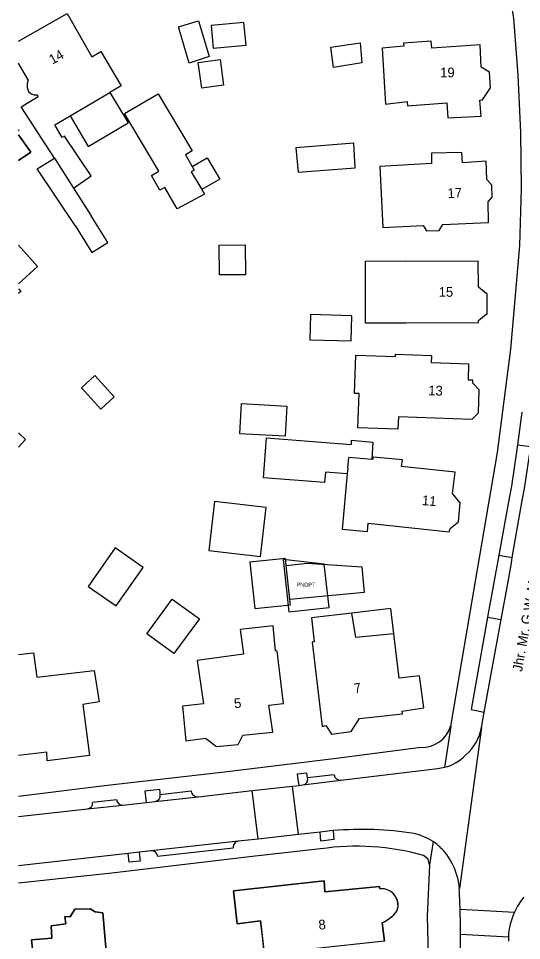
# Model space of a CAD drawing. Extents: x 194485 to 197793, y 468269 to 470822.
# Drawn here: x 194485.4 to 194547.5, y 470088.6 to 470202.3 of the extents above; entities that cross this region are included whole.
import ezdxf

# ---------------------------------------------------------------- set-up
doc = ezdxf.new("R2010")
doc.units = 0
for name, color, linetype in [('BAG plantopografie panden grensvlak pand', 7, 'Continuous'), ('BAG plantopografie panden kenmerkpunt', 7, 'Continuous'), ('BGT grensvlak gebouwinstallatie plus 1', 7, 'Continuous'), ('BGT grensvlak overig bouwwerk uitbreiding populatie', 7, 'Continuous'), ('BGT grensvlak pand op maaiveld', 7, 'Continuous'), ('BGT grensvlak pand op maaiveld LR', 7, 'Continuous'), ('BGT grensvlak wegdeel', 7, 'Continuous'), ('BGT tekst huisnummerreeks', 7, 'Continuous'), ('BGT tekst openbare ruimte label weg', 7, 'Continuous'), ('GEM grensvlak beperking object', 7, 'Continuous')]:
    doc.layers.add(name, color=color, linetype=linetype)

msp = doc.modelspace()

# ---------------------------------------------------------------- linework, layer by layer
at = {"layer": 'BAG plantopografie panden grensvlak pand'}
msp.add_lwpolyline([(194518.04, 470135.61), (194518.74, 470129.14), (194523.71, 470129.68), (194523.13, 470135.03), (194518.04, 470135.61)], dxfattribs=at)
at = {"layer": 'BGT grensvlak gebouwinstallatie plus 1'}
for p, q in [((194496.69, 470193.16), (194498.93, 470189.43)), ((194506.84, 470184.06), (194508.7, 470185.11)), ((194508.7, 470185.11), (194510.26, 470182.48)), ((194510.26, 470182.48), (194508.03, 470181.19)), ((194487.77, 470171.73), (194485.41, 470174.33)), ((194485.41, 470169.59), (194487.77, 470171.73)), ((194526.46, 470150.3), (194526.42, 470149.77)), ((194526.46, 470150.3), (194529.12, 470150.08)), ((194529.12, 470150.08), (194528.97, 470147.94)), ((194525.96, 470146.17), (194523.27, 470146.38)), ((194501.25, 470126.44), (194504.37, 470130.72)), ((194504.37, 470130.72), (194507.72, 470128.28)), ((194507.72, 470128.28), (194504.59, 470124)), ((194504.59, 470124), (194501.25, 470126.44))]:
    msp.add_line(p, q, dxfattribs=at)
for points in [[(194491.77, 470190.27), (194494.03, 470186.5), (194498.93, 470189.43)], [(194523.27, 470146.38), (194523.17, 470145.09), (194515.62, 470145.68), (194516, 470150.59), (194526.42, 470149.77)], [(194497.35, 470137.03), (194494.03, 470132.29), (194497.48, 470129.88), (194500.79, 470134.61), (194497.35, 470137.03)], [(194531.72, 470126.43), (194531.35, 470129.55), (194526.54, 470128.98)]]:
    msp.add_lwpolyline(points, dxfattribs=at)
at = {"layer": 'BGT grensvlak overig bouwwerk uitbreiding populatie'}
for p, q in [((194507.59, 470196.86), (194510.27, 470197.23)), ((194508.04, 470193.7), (194507.59, 470196.86)), ((194510.27, 470197.23), (194510.71, 470194.08)), ((194510.71, 470194.08), (194508.04, 470193.7)), ((194510.18, 470174.35), (194513.36, 470174.37)), ((194510.2, 470170.68), (194510.18, 470174.35)), ((194513.36, 470174.37), (194513.39, 470170.7)), ((194513.39, 470170.7), (194510.2, 470170.68)), ((194493.17, 470156.77), (194494.82, 470158.28)), ((194494.82, 470158.28), (194497.21, 470155.64)), ((194495.56, 470154.14), (194493.17, 470156.77)), ((194497.21, 470155.64), (194495.56, 470154.14)), ((194485.41, 470151.2), (194486.28, 470150.38)), ((194486.28, 470150.38), (194485.41, 470149.46))]:
    msp.add_line(p, q, dxfattribs=at)
at = {"layer": 'BGT grensvlak pand op maaiveld'}
for p, q in [((194486.63, 470194.74), (194485.41, 470196.8)), ((194491.77, 470190.27), (194496.69, 470193.16)), ((194506.72, 470183.38), (194508.03, 470181.19)), ((194492.22, 470181.37), (194494.39, 470177.97)), ((194526.03, 470146.85), (194526.15, 470148.17)), ((194528.97, 470147.94), (194526.15, 470148.17)), ((194526.03, 470146.85), (194525.96, 470146.17))]:
    msp.add_line(p, q, dxfattribs=at)
for points in [[(194485.41, 470199.49), (194491.4, 470202.92), (194494.46, 470197.58), (194495.57, 470198.23), (194498.08, 470193.97), (194496.69, 470193.16)], [(194505.15, 470201.27), (194507.62, 470201.98), (194508.94, 470197.61), (194506.45, 470196.8), (194505.15, 470201.27)], [(194509.43, 470198.63), (194513.48, 470198.99), (194513.22, 470201.8), (194509.17, 470201.44), (194509.43, 470198.63)], [(194524.28, 470196.25), (194523.92, 470198.75), (194527.54, 470199.27), (194527.74, 470196.81), (194524.28, 470196.25)], [(194542.49, 470190.26), (194542.3, 470192.22), (194542.64, 470192.24), (194543.64, 470193.72), (194543.5, 470195.68), (194542.48, 470196.3), (194542.33, 470199.02), (194536.37, 470198.62), (194536.29, 470199.48), (194532.91, 470199.24), (194532.93, 470198.89), (194530.27, 470198.63), (194530.67, 470191.74), (194533.36, 470192.07), (194533.38, 470191.51), (194538.24, 470191.89), (194538.38, 470190.03), (194542.49, 470190.26)], [(194486.63, 470194.74), (194486.48, 470194.28), (194486.48, 470193.79), (194486.65, 470193.28), (194486.99, 470193), (194487.37, 470192.87), (194487.73, 470192.87)], [(194489.84, 470185.07), (194485.76, 470191.4), (194487.85, 470192.67), (194487.73, 470192.87)], [(194503.47, 470181.47), (194502.86, 470181.11), (194501.81, 470182.95), (194502.74, 470183.48), (194498.49, 470190.58), (194502.63, 470193.02), (194506.83, 470185.97), (194506.01, 470185.49), (194506.84, 470184.06)], [(194492.22, 470181.37), (194494.38, 470182.88), (194491.09, 470187.8), (194490.79, 470187.6), (194489.89, 470189.17), (194491.77, 470190.27)], [(194485.41, 470188.43), (194485.48, 470188.47), (194485.41, 470188.56)], [(194485.41, 470184.78), (194486.92, 470185.83), (194485.41, 470187.93)], [(194526.95, 470183.88), (194526.77, 470186.93), (194519.62, 470186.36), (194519.92, 470183.36), (194526.95, 470183.88)], [(194492.41, 470176.76), (194487.73, 470183.74), (194489.84, 470185.07)], [(194543.36, 470177.15), (194543.32, 470179.7), (194543.82, 470180.27), (194543.8, 470181.76), (194543.15, 470182.42), (194543.07, 470184.7), (194540.17, 470184.51), (194540.1, 470185.75), (194536.33, 470185.68), (194536.34, 470184.41), (194529.96, 470184.04), (194530.33, 470176.51), (194535.31, 470176.76), (194535.73, 470176.11), (194537.31, 470176.17), (194537.73, 470176.91), (194543.36, 470177.15)], [(194506.84, 470184.06), (194507.1, 470183.61), (194506.72, 470183.38)], [(194508.03, 470181.19), (194508.37, 470180.63), (194504.99, 470178.83), (194503.47, 470181.47)], [(194492.41, 470176.76), (194494.45, 470173.45), (194496.43, 470174.67), (194494.39, 470177.97)], [(194533.22, 470164.79), (194533.22, 470164.74), (194528.22, 470164.73), (194528.19, 470172.38), (194533.08, 470172.4), (194533.08, 470172.35)], [(194533.22, 470164.79), (194542.15, 470164.83), (194542.15, 470165.05), (194543.1, 470165.83), (194543.2, 470165.83), (194543.19, 470168.39), (194543.09, 470168.39), (194542.14, 470169.17), (194542.12, 470172.38), (194533.08, 470172.35)], [(194485.41, 470168.95), (194485.7, 470168.64), (194485.41, 470168.38)], [(194526.43, 470162.54), (194526.52, 470165.64), (194521.42, 470165.78), (194521.33, 470162.68), (194526.43, 470162.54)], [(194541.3, 470152.87), (194532.27, 470153.18), (194532.21, 470151.67), (194527.27, 470151.84), (194527.41, 470156.05), (194526.86, 470156.07), (194527.02, 470160.78), (194531.86, 470160.62)], [(194541.3, 470152.87), (194542.15, 470153.66), (194542.24, 470156.5), (194541.45, 470157.35), (194541.46, 470157.69), (194540.89, 470157.71), (194540.95, 470159.67), (194536.36, 470159.83), (194536.39, 470160.7), (194531.87, 470160.85), (194531.86, 470160.62)], [(194518.32, 470150.8), (194512.71, 470151.1), (194512.91, 470154.82)], [(194512.91, 470154.82), (194518.51, 470154.52), (194518.32, 470150.8)], [(194525.96, 470146.17), (194525.35, 470139.32), (194528.44, 470139.06), (194528.55, 470140.08), (194538.54, 470139.02), (194538.63, 470139.44), (194539.68, 470140.24), (194539.89, 470142.6), (194538.92, 470143.72), (194539.26, 470146.35), (194532.66, 470147.07), (194532.77, 470147.89), (194529.14, 470148.2), (194529.08, 470147.93), (194528.97, 470147.94)], [(194515.27, 470135.99), (194515.96, 470142.02), (194509.59, 470142.75), (194508.9, 470136.72), (194515.27, 470135.99)], [(194518.43, 470134.84), (194518.34, 470135.72), (194513.96, 470135.26), (194514.57, 470129.55), (194518.94, 470130.01), (194518.88, 470130.66)], [(194518.43, 470134.84), (194521.01, 470135.15), (194527.75, 470134.7), (194528.04, 470131.55), (194518.88, 470130.66)], [(194526.54, 470128.98), (194521.56, 470128.41), (194521.89, 470125.44), (194521.63, 470125.42), (194522.87, 470115.03), (194523.33, 470115.13), (194524.02, 470114.09), (194526.42, 470114.38)], [(194531.72, 470126.43), (194527, 470126), (194526.54, 470128.98)], [(194512.52, 470112.78), (194513.1, 470113.94), (194516.78, 470114.33), (194516.27, 470117.64), (194518.08, 470117.86), (194517.33, 470124.32), (194517.13, 470124.34), (194516.84, 470127.41), (194512.77, 470126.96), (194513.17, 470123.94), (194507.45, 470123.16), (194508.25, 470117.8), (194505.63, 470117.53), (194506.07, 470113.25), (194508.48, 470113.56), (194509.82, 470112.54), (194512.52, 470112.78)], [(194526.42, 470114.38), (194527.47, 470115.99), (194532.77, 470116.58), (194532.74, 470116.89), (194535.39, 470117.31), (194534.87, 470121.27), (194532.36, 470120.99), (194531.72, 470126.43)], [(194485.41, 470123.87), (194487.26, 470124.1), (194487.68, 470121.11), (194494.76, 470121.9), (194495.36, 470118.07), (194493.36, 470117.73), (194494.18, 470111.46)], [(194494.18, 470111.46), (194488.97, 470110.78), (194488.9, 470111.85), (194485.41, 470111.43)], [(194530.28, 470090.83), (194530.54, 470088.54), (194521.38, 470087.58), (194521.74, 470084.25), (194513.83, 470083.49), (194513.4, 470086.9), (194515.72, 470087.08), (194515.49, 470089.18), (194515.28, 470091.04), (194512.37, 470090.67), (194511.93, 470094.75), (194523.11, 470096.01), (194523.2, 470094.65), (194529.94, 470095.3), (194529.97, 470095.01)], [(194496.66, 470082.58), (194495.83, 470092.04), (194494.89, 470092.17), (194494.27, 470092.55), (194492.37, 470092.48), (194491.81, 470091.55), (194491.14, 470091.58), (194491.27, 470090.69), (194489.44, 470090.43), (194489.51, 470088.92), (194487.02, 470088.71), (194487.67, 470082.9)]]:
    msp.add_lwpolyline(points, dxfattribs=at)
for centre, radius, start, end in [((194530.18, 470092.97), 2.04, 66.6153, 95.8839), ((194530.17, 470092.98), 2.05, 22.5532, 66.2765), ((194530.33, 470092.98), 1.9, 336.9753, 24.3772), ((194528.36, 470095.12), 4.7, 294.0189, 322.132)]:
    msp.add_arc(centre, radius, start, end, dxfattribs=at)
at = {"layer": 'BGT grensvlak pand op maaiveld LR'}
for p, q in [((194489.84, 470185.07), (194492.22, 470181.37)), ((194518.88, 470130.66), (194518.43, 470134.84))]:
    msp.add_line(p, q, dxfattribs=at)
at = {"layer": 'BGT grensvlak wegdeel'}
for p, q in [((194547.47, 470153.76), (194546.93, 470149.75)), ((194546.93, 470149.75), (194546.23, 470144.65)), ((194546.93, 470149.75), (194548.58, 470149.53)), ((194546.23, 470144.65), (194545.94, 470143.16)), ((194545.94, 470143.16), (194544.66, 470136.15)), ((194544.66, 470136.15), (194543.26, 470128.5)), ((194544.66, 470136.15), (194546.31, 470135.84)), ((194542.82, 470116.79), (194544.93, 470128.19)), ((194543.26, 470128.5), (194544.93, 470128.19)), ((194542.5, 470114.91), (194542.82, 470116.79)), ((194538.71, 470115.06), (194537.93, 470109.98)), ((194542.5, 470114.91), (194539.78, 470095.06)), ((194535.05, 470112.43), (194524.65, 470111.09)), ((194525.17, 470108.4), (194537.1, 470109.85)), ((194524.34, 470109.05), (194521.07, 470108.68)), ((194514.22, 470107.11), (194519.19, 470107.67)), ((194519.19, 470107.67), (194519.98, 470107.76)), ((194519.93, 470101.7), (194519.19, 470107.67)), ((194519.98, 470107.76), (194520.5, 470107.81)), ((194520.5, 470107.81), (194525.17, 470108.4)), ((194502.27, 470105.78), (194507.56, 470106.36)), ((194506.72, 470107.06), (194502.9, 470106.6)), ((194507.56, 470106.36), (194514.22, 470107.11)), ((194514.96, 470101.14), (194514.22, 470107.11)), ((194493.92, 470104.85), (194498.29, 470105.33)), ((194494.56, 470105.67), (194497.49, 470106.03)), ((194498.29, 470105.33), (194501.17, 470105.66)), ((194501.17, 470105.66), (194502.27, 470105.78)), ((194485.41, 470103.92), (194493.92, 470104.85)), ((194522.6, 470102), (194519.93, 470101.7)), ((194524.23, 470102.18), (194522.6, 470102)), ((194512.52, 470100.87), (194501.78, 470099.69)), ((194514.96, 470101.14), (194512.52, 470100.87)), ((194519.93, 470101.7), (194514.96, 470101.14)), ((194536.54, 470100.84), (194536.1, 470097.98)), ((194501.78, 470099.69), (194500.29, 470099.53)), ((194502.57, 470099.04), (194511.9, 470100.07)), ((194498.96, 470099.38), (194485.41, 470097.86)), ((194500.29, 470099.53), (194498.96, 470099.38)), ((194539.88, 470092.49), (194546.58, 470092.14)), ((194539.92, 470089.4), (194545.83, 470089.08))]:
    msp.add_line(p, q, dxfattribs=at)
for points in [[(194538.71, 470115.06), (194541.76, 470132.92), (194544.49, 470148.78), (194546.12, 470161.52), (194547.24, 470174.3), (194547.43, 470181.27), (194547.35, 470188.24), (194547.04, 470195.29), (194546.51, 470202.32), (194543.84, 470218.01)], [(194546.31, 470135.84), (194547.52, 470142.86), (194547.81, 470144.34), (194548.58, 470149.53)], [(194544.93, 470128.19), (194545.67, 470132.2), (194546.2, 470135.15), (194546.31, 470135.84)], [(194543.26, 470128.5), (194541.25, 470117.13), (194542.82, 470116.79)], [(194524.65, 470111.09), (194510.82, 470109.39), (194496.03, 470107.7), (194485.41, 470106.38)], [(194521.07, 470108.68), (194520.99, 470109.28), (194519.8, 470109.12), (194519.88, 470108.53), (194519.98, 470107.76)], [(194502.9, 470106.6), (194502.87, 470106.9), (194502.83, 470107.23), (194501, 470107.06), (194501.17, 470105.66)], [(194524.23, 470102.18), (194524.3, 470101.07), (194522.7, 470100.9), (194522.6, 470102)], [(194522.67, 470099.94), (194514.61, 470099.05), (194496.91, 470096.93), (194485.41, 470095.69)], [(194500.29, 470099.53), (194500.41, 470098.43), (194499.07, 470098.29), (194498.96, 470099.38)], [(194536.1, 470097.98), (194535.93, 470098.68), (194535.36, 470099.13)], [(194536.1, 470097.98), (194535.82, 470091.6), (194535.96, 470085.36), (194536.77, 470077.26), (194537.92, 470069.2), (194543.74, 470039.31)]]:
    msp.add_lwpolyline(points, dxfattribs=at)
for centre, radius, start, end in [((194535.16, 470116.13), 3.7, 268.1998, 343.2065), ((194536.98, 470115.79), 5.59, 310.0632, 350.935), ((194536.68, 470115.21), 5.37, 283.4937, 316.6179), ((194536.67, 470115.27), 5.43, 274.6011, 283.4717), ((194520.37, 470108.51), 0.714, 280.3741, 14.2875), ((194525.12, 470109.18), 0.787, 189.3304, 274.0759), ((194502.15, 470106.52), 0.755, 279.0586, 6.1667), ((194507.49, 470107.13), 0.774, 184.8553, 274.985), ((194493.82, 470105.59), 0.744, 277.2792, 5.9174), ((194498.24, 470106.09), 0.755, 184.3586, 273.3816), ((194527.77, 470061.02), 41.31, 81.0535, 94.9102), ((194532.55, 470094.7), 7.31, 57.0045, 77.0244), ((194512.61, 470100.16), 0.714, 97.1147, 187.9062), ((194532.02, 470094.3), 7.94, 43.1335, 55.3852), ((194501.85, 470098.97), 0.724, 5.0514, 95.8926), ((194527.08, 470069.33), 30.92, 74.4757, 98.2002), ((194531.65, 470094.39), 8.16, 4.7217, 40.8765), ((194412.83, 470088.98), 127.09, 1.5839, 2.7424), ((194554.15, 470088.66), 8.33, 140.246, 155.3379), ((194420.08, 470089.32), 119.84, 0.0351, 1.5174), ((194554.2, 470088.64), 8.39, 155.362, 176.9981), ((194417.89, 470089.39), 122.03, 358.8636, 0.0004), ((194554.88, 470088.65), 9.06, 177.2331, 180.6412)]:
    msp.add_arc(centre, radius, start, end, dxfattribs=at)
at = {"layer": 'GEM grensvlak beperking object'}
for points in [[(194485.41, 470188.56), (194485.48, 470188.47), (194485.41, 470188.43)], [(194485.41, 470187.93), (194486.92, 470185.83), (194485.41, 470184.78)], [(194485.41, 470123.87), (194487.26, 470124.1), (194487.68, 470121.11), (194494.76, 470121.9), (194495.36, 470118.07), (194493.36, 470117.73), (194494.18, 470111.46), (194488.97, 470110.78), (194488.9, 470111.85), (194485.41, 470111.43)], [(194530.54, 470088.54), (194530.28, 470090.83), (194530.79, 470091.1), (194531.26, 470091.42), (194531.69, 470091.8), (194532.07, 470092.24), (194532.17, 470092.53), (194532.22, 470092.84), (194532.21, 470093.16), (194532.16, 470093.47), (194532.05, 470093.76), (194531.87, 470094.1), (194531.63, 470094.41), (194531.33, 470094.66), (194530.99, 470094.85), (194530.66, 470094.96), (194530.32, 470095.01), (194529.97, 470095.01), (194529.94, 470095.3), (194523.2, 470094.65), (194523.11, 470096.01), (194511.93, 470094.75)], [(194511.93, 470094.75), (194512.37, 470090.67), (194515.28, 470091.04), (194515.72, 470087.08)], [(194487.67, 470082.9), (194487.02, 470088.71), (194489.51, 470088.92), (194489.44, 470090.43), (194491.27, 470090.69), (194491.14, 470091.58), (194491.81, 470091.55), (194492.37, 470092.48), (194494.27, 470092.55), (194494.89, 470092.17), (194495.83, 470092.04), (194496.66, 470082.58)]]:
    msp.add_lwpolyline(points, dxfattribs=at)

# ---------------------------------------------------------------- texts
at = {"layer": 'BAG plantopografie panden kenmerkpunt'}
msp.add_text('PNDPT', height=0.5, dxfattribs=at).set_placement((194519.7, 470132.24))
at = {"layer": 'BGT tekst huisnummerreeks'}
for s, rotation, p in [('14', 29.8, (194489.6, 470196.59)), ('19', 359.8, (194537.41, 470195.04)), ('17', 2.2, (194538.34, 470180.14)), ('15', 0.2, (194537.24, 470167.98)), ('13', 358, (194535.93, 470155.85)), ('11', 355, (194535.13, 470142.32)), ('7', 8.9, (194526.87, 470119.1)), ('5', 6, (194512.06, 470117.25)), ('8', 5.5, (194522.47, 470089.96))]:
    msp.add_text(s, height=1.2, rotation=rotation, dxfattribs=at).set_placement(p)
at = {"layer": 'BGT tekst openbare ruimte label weg'}
msp.add_text('Jhr. Mr. G.W. Molleruslaan', height=1.2, rotation=79.9, dxfattribs=at).set_placement((194547.5, 470121.72))

doc.saveas('drawing.dxf')
